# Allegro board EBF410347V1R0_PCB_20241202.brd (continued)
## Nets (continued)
GND: C3.2 C4.2 C5.2 C6.2 C7.2 C8.2 C9.2 C13.2 C14.2 C16.2 C17.2 C18.2 C19.2 C20.2 C21.2 C23.2 C24.2 C26.2 C27.2 C28.2 C29.2 C30.2 C31.2 C32.2 C33.2 C35.1 C36.2 C37.2 C38.2 C39.2 C40.2 C41.2 C42.2 C43.2 C44.2 C45.2 C47.1 C48.2 C49.2 C50.2 C51.2 C52.2 C53.2 C62.1 C65.2 C66.2 C67.2 C68.2 C69.2 C70.2 C71.2 C72.2 C73.2 C74.2 C75.2 C76.2 C77.2 C78.2 C79.2 C80.2 C81.2 C82.2 C83.2 C84.2 C85.2 C86.2 C87.2 C88.2 C89.2 C90.2 C91.2 C92.2 C93.2 C94.2 C95.2 C96.2 C97.2 C98.2 C99.2 C100.2 C101.2 C102.2 C103.2 C104.2 C105.2 C106.2 C107.2 C108.2 C109.2 C110.2 C111.2 C112.2 C113.2 C115.2 C116.2 C117.2 C118.2 C119.2 C120.2 C121.2 C122.2 C123.2 C124.2 C125.2 C126.2 C127.2 C128.2 C129.2 C130.2 C131.2 C132.2 C133.2 C134.2 C135.2 C136.2 C137.2 C138.2 C139.2 C140.2 C141.2 C142.2 C143.2 C144.2 C145.2 C146.2 C147.2 C150.2 C153.2 C154.2 C155.2 C156.2 C157.2 C158.2 C159.2 C160.2 C161.2 C162.2 C164.2 C165.2 CN1.2 CN1.3 D1.2 D2.2 D3.2 D4.2 D5.2 D6.2 D7.2 D8.2 D9.1 D10.1 D11.1 D12.1 D13.1 D14.1 D15.1 D16.1 D17.2 D18.2 D19.2 D20.2 D21.2 D22.2 D23.2 D24.2 D25.2 D26.2 D27.2 D28.2 D29.2 D30.2 D31.2 D32.2 D33.2 D34.2 D35.2 D36.2 D37.2 D38.2 D39.2 D40.2 D41.2 D42.2 D44.1 D47.2(A) D48.2 D49.2 D50.2 D51.2 D52.2 D53.2 D55.2 D56.2 D57.2 D58.2 D59.2 D60.2 D61.2 D62.2 D63.2 D64.2 D65.2 D67.2 D68.2 D69.2 D70.2 D71.2 D72.2 D73.2 D74.2 D75.2 D76.2 J1.2 J1.3 J2.1 J2.2 J2.5(SH1) J2.6(SH2) J3.3 J3.4 J3.6 J3.10 J3.14 J3.17 J3.20 J3.24 J3.29 J3.37 J3.50 J3.53 J3.75 J3.84 J3.87 J3.92 J3.95 J3.98 J3.101 J3.106 J3.109 J3.114 J3.117 J3.122 J3.125 J3.130 J3.133 J3.136 J3.145 J3.146 J3.147 J3.150 J3.151 J3.154 J3.157 J3.160 J3.163 J3.166 J3.173 J3.181 J3.187 J3.192 J3.195 J5.2 J7.6(VSS) J7.10(GND10) J7.11(GND11) J7.12(GND12) J7.13(GND13) J8.5(SH1) J8.6(SH2) J9.4(GND1) J9.7(GND2) J11.2 J12.4(GND) J13.4(GND) J14.1 J14.5(SH1) J14.6(SH2) J15.3 J16.4 J17.4 J17.5 J17.6 J17.13 J17.14 J17.25 J17.26 J18.6 J18.7 J18.8 J18.16 J18.19 J18.22 J18.25 J18.28 J18.31(SH1) J18.32(SH2) J19.1 J19.7(SH1) J19.8(SH2) J21.2 J21.5 J21.7(SH1) J21.8(SH2) J22.1 J22.7(SH1) J22.8(SH2) J23.2 J24.4 J24.23 J24.24 J24.25(SH1) J24.26(SH2) J25.2 J26.8 J26.9(SH1) J26.10(SH2) J27.7 J27.8 J28.4 J28.23 J28.24 J28.25(SH1) J28.26(SH2) J29.4 J29.23 J29.24 J29.25(SH1) J29.26(SH2) J30.4 J30.23 J30.24 J30.25(SH1) J30.26(SH2) J31.5 J31.6 J31.7(SH1) J31.8(SH2) J32.4 J33.4 J33.5(SH1) J33.6(SH2) J34.4 J34.5(SH1) J34.6(SH2) J35.4 J36.4 J37.4 J37.5(SH1) J37.6(SH2) J38.1 J38.5(SH1) J38.6(SH2) L2.2 L10.1 L11.1 L12.1 LED1.1(CATHODE) Q2.2(EMITTER) R2.2 R4.2 R7.2 R9.2 R11.2 R16.2 R17.2 R27.1 R28.2 R29.2 R38.1 R40.2 R50.2 R51.1 R57.2 R59.2 R66.2 R68.2 R76.1 R77.1 R85.2 R111.2 R112.2 R121.2 R122.2 R129.2 R138.2 R163.2 R173.2 R180.2 R181.2 SS1.1(NC_1) SS2.1(NC_1) SS3.1(NC_1) SS4.1(NC_1) SW1.3(B1) SW1.4(B2) T2.1 T2.3 T4.1 T4.3 T6.1 T6.3 T8.1 T8.3 U1.1(GND) U2.1(GND) U3.1(GND) U4.1(GND) U5.7(GND) U5.9(EPAD) U6.7(GND) U6.9(EPAD) U7.2(GND) U8.25(VSS) U9.2(GND) U10.5(GND) U10.9(RESERVE) U10.37(VSS_PLL) U10.49(EPAD) U11.1(\\O\E) U11.3(GND) U12.1(\\O\E) U12.3(GND) U13.2(GND) U14.2(GND) U15.4(VSS) U16.1(GND1) U16.3(GND3) U16.20(GND20) U16.31(GND31) U16.33(GND33) U16.36(GND36) U17.2(A1) U17.3(A2) U17.12(GND) U18.2(GND) U18.8(S) U19.2(GND) U19.8(S) U21.2(GND) U22.2(GND) U23.15(GND) U24.5(GND) U25.15(GND) U26.5(GND) U27.2(GND) Y1.2(GND1) Y1.4(GND2) Y2.2(GND) Y4.2(GND)
VCC3V3_SD: C52.1 C53.1 D8.1 J3.8 J7.4(VDD)
VCC3V3_WIFI: C121.1 C122.1 C123.1 C124.1 C125.1 C126.1 C127.1 R151.1 R164.1 R167.2 U16.9(VDD33) U16.22(VDDIO) Y4.4(VCC)
VCC5V0_SYS: C12.2 C13.1 C14.1 J3.1 J3.2 L3.2 R5.2 R12.1
VCC5V0_USB: C15.2 C16.1 C17.1 L4.2 R6.2 U7.5(IN) U9.5(IN)
VCC5V0_USB20_HUB: C75.1 C76.1 C78.1 C79.1 C80.1 C137.1 J12.1(VBUS) J13.1(VBUS) J14.4 J38.4 U9.1(OUT)
VCC_LVDS: J17.1 J17.2 J17.3 J20.2 J20.4 J20.6
VCC_RTC: C117.1 D43.3 R130.1 R131.1 U15.8(VDD)
VCCA_1V8: J3.7 J26.1 J27.1 R171.1
VCCIO_ACODEC: J3.9 R18.2
VDD_3V3: C23.1 C24.1 C25.2 C68.1 C81.1 C85.1 C106.1 C107.1 C110.1 C111.1 C128.1 C136.1 C141.1 C157.1 C159.1 C160.1 D42.1 D43.2 J19.6 J21.4 L5.2 L13.1 L14.2 L15.1 L16.2 L17.1 R10.2 R13.1 R14.2 R15.2 R31.2 R60.1 R78.1 R80.1 R82.1 R167.1 R174.1 R175.1 R188.1 R189.1 R190.1 R191.1 R192.1 R260.1 U11.5(VCC) U12.5(VCC) U14.5(IN) U17.24(VCC) U18.5(VIO) U19.5(VIO) U21.1(VCCA) U21.5(DIR) U22.1(VCCA) U22.5(DIR) U27.1(VIN) U27.3(EN)
VDD_5V: C2.2 C3.1 C4.1 C132.1 C143.1 C158.1 C161.1 L1.2 R1.2 R21.1 R32.1 R84.1 R132.1 R168.1 R169.1 R170.1 R172.1 R259.1 U13.5(IN) U18.3(VCC) U19.3(VCC) U21.6(VCCB) U22.6(VCCB)
VDD_CAM0_5V: C108.1 C109.1 J24.1 J24.2 J24.3 R172.2
VDD_CAM1_5V: C129.1 C130.1 J28.1 J28.2 J28.3 R168.2
VDD_CAM2_5V: C134.1 C135.1 J29.1 J29.2 J29.3 R170.2
VDD_CAM3_5V: C131.1 C133.1 J30.1 J30.2 J30.3 R169.2
VDD_IO: D75.1 J22.6 R259.2 R260.2
VDD_LCD_3V3: C82.1 C139.1 C140.1 J18.4 J18.5 R176.1 R177.1 U14.1(OUT)
VDD_LCD_5V: C83.1 C84.1 C86.1 J18.1 J18.2 J18.3 U13.1(OUT)
VDD_LVDS: C100.1 C101.1 C102.1 C103.1 C142.1 C164.1 U10.35(VDD_LVDS1) U10.36(VDD_PLL) U10.38(VDD_LVDS2) U27.5(VOUT) Y2.4(VCC)
VDDIO_LVDS: C91.1 C92.1 C93.1 C94.1 C112.1 C113.1 L13.2 R73.1 U10.10(VDDIO) U10.13(VDD_RX)
BAT_RTC: C116.1 D43.1 D44.2 J23.1
BT_HOST_WAKE: J3.46 R158.1
BT_REG_ON: J3.47 R155.2
BT_UART_CTS: R154.2 U16.44(UART_CTS_N)
BT_UART_RTS: R129.1 R150.2 U16.41(UART_RTS_N)
BT_UART_RXD: R153.2 U16.43(UART_RXD)
BT_UART_TXD: R152.2 U16.42(UART_TXD)
BT_WAKE: J3.45 R156.1
CAM0_NRST: J24.22 U17.5(P0_1)
CAM0_PWDN: J24.15 U17.4(P0_0)
CAM1_NRST: J28.22 U17.7(P0_3)
CAM1_PWDN: J28.15 U17.6(P0_2)
CAM2_NRST: J29.22 U17.9(P0_5)
CAM2_PWDN: J29.15 U17.8(P0_4)
CAM3_NRST: J30.22 U17.11(P0_7)
CAM3_PWDN: J30.15 U17.10(P0_6)
CAN0_H: R237.1 R238.1 U18.7(CANH)
CAN0_L: R237.2 R251.1 U18.6(CANL)
CAN0_RX_M2: R240.1 R243.2
CAN0_TX_M2: R239.1 R241.2
CAN1_H: R247.1 R252.1 U19.7(CANH)
CAN1_L: R247.2 R258.1 U19.6(CANL)
CAN1_RX_M1: R246.1 R257.2
CAN1_TX_M1: R245.1 R248.2
CLK_32K_IN: J3.200 R135.2
DGB_RX: D30.1 J15.2 R70.1
DGB_TX: D31.1 J15.1 R69.1
ETH_PHY_LED1: J3.164 J10.10(LED_Y+)
ETH_PHY_LED2: J3.165 J10.12(LED_G+)
ETH_PHY_MDIN0: C55.1 J3.153
ETH_PHY_MDIN1: C57.1 J3.156
ETH_PHY_MDIN2: C59.1 J3.159
ETH_PHY_MDIN3: C61.1 J3.162
ETH_PHY_MDIP0: C54.1 J3.152
ETH_PHY_MDIP1: C56.1 J3.155
ETH_PHY_MDIP2: C58.1 J3.158
ETH_PHY_MDIP3: C60.1 J3.161
EXT_PWR_EN: J3.13 R3.2
FAN_CTRL: J3.40 R137.1
GM8775C_DA0N: R89.2 U10.15(DA0N)
GM8775C_DA0P: R86.2 U10.14(DA0P)
GM8775C_DA1N: R93.2 U10.17(DA1N)
GM8775C_DA1P: R90.2 U10.16(DA1P)
GM8775C_DA2N: R97.2 U10.21(DA2N)
GM8775C_DA2P: R94.2 U10.20(DA2P)
GM8775C_DA3N: R102.2 U10.23(DA3N)
GM8775C_DA3P: R99.2 U10.22(DA3P)
GM8775C_DACN: R107.2 U10.19(DACN)
GM8775C_DACP: R104.2 U10.18(DACP)
GM8775C_RSTN: C95.1 R73.2 R187.2 U10.12(EN)
GPIO0_C0: J3.38 R248.1 R253.1
GPIO0_C1: J3.39 R255.1 R257.1
GPIO0_C6: J3.43 R241.1 R242.1
GPIO0_C7: J3.44 R243.1 R244.1
GPIO0C0: R253.2 R254.1
GPIO0C1: R255.2 R256.1
GPIO0C6: R242.2 R249.1
GPIO0C7: R244.2 R250.1
HP_BUTTON_DET: C40.1 J3.33 R26.2 R29.1
HP_PLUG_IN_DET: J3.196 R36.2
HP_SNS: J3.22 R38.2
HPL_OUT: C34.1 J3.21 R33.2
HPR_OUT: C46.1 J3.23 R34.2
I2C0_SCL: J3.194 J24.6 U15.6(SCL) U17.22(SCL)
I2C0_SDA: J3.193 J24.5 U15.5(SDA) U17.23(SDA)
I2C1_SCL_M1: J3.57 J18.9 J19.4 J28.6 R74.1 R174.2
I2C1_SDA_M1: J3.58 J18.10 J19.5 J28.5 R75.1 R175.2
I2C2_SCL_M1: J3.55 J29.6 R189.2
I2C2_SDA_M1: J3.56 J29.5 R190.2
I2C5_SCL_M1: J3.148 J30.6 R191.2
I2C5_SDA_M1: J3.149 J30.5 R192.2
I2S2_LRCK_M0: J3.182 R157.2
I2S2_SCLK_M0: J3.184 R160.2
I2S2_SDI_M0: J3.185 R161.2
I2S2_SDO_M0: J3.186 R159.2
IO0_C0: D74.1 J22.5 R252.2 R254.2
IO0_C1: D37.1 J22.4 R256.2 R258.2
IO0_C6: D36.1 J22.3 R238.2 R249.2
IO0_C7: D35.1 J22.2 R250.2 R251.2
LCD_BL_PWM: J3.64 R184.1 R185.1
LCD_CPT_INT: J3.60 R81.1 R178.1
LCD_CPT_RST: J3.59 R182.1 R183.1
LCD_RST: J3.63 R186.1 R187.1
LED_BLUE: J3.183 R103.1
LED_RED: R98.1 U17.13(P1_0)
LVDS_3V3: C96.1 C97.1 J20.5 R78.2
LVDS_5V: C104.1 C105.1 J20.3 R84.2
LVDS_12V: C98.1 C99.1 J20.1 J31.1 J31.2 R79.2
LVDS_BL_EN: J3.54 R213.1 U21.3(A1)
LVDS_BL_PWM: R185.2 R214.1 U22.3(A1)
LVDS_BLEN: J31.3 R213.2 R215.2
LVDS_BLPWM: J31.4 R214.2 R216.2
LVDS_CPT_INT: J19.3 R80.2 R178.2
LVDS_CPT_RST: J19.2 R82.2 R183.2
LVDS_TXA_CLKN: J17.15 U10.27(A_CLKN)
LVDS_TXA_CLKP: J17.16 U10.28(A_CLKP)
LVDS_TXA_D0N: J17.7 U10.33(A_Y0N)
LVDS_TXA_D0P: J17.8 U10.34(A_Y0P)
LVDS_TXA_D1N: J17.9 U10.31(A_Y1N)
LVDS_TXA_D1P: J17.10 U10.32(A_Y1P)
LVDS_TXA_D2N: J17.11 U10.29(A_Y2N)
LVDS_TXA_D2P: J17.12 U10.30(A_Y2P)
LVDS_TXA_D3N: J17.17 U10.25(A_Y3N)
LVDS_TXA_D3P: J17.18 U10.26(A_Y3P)
LVDS_TXB_CLKN: J17.27 U10.41(B_CLKN)
LVDS_TXB_CLKP: J17.28 U10.42(B_CLKP)
LVDS_TXB_D0N: J17.19 U10.47(B_Y0N)
LVDS_TXB_D0P: J17.20 U10.48(B_Y0P)
LVDS_TXB_D1N: J17.21 U10.45(B_Y1N)
LVDS_TXB_D1P: J17.22 U10.46(B_Y1P)
LVDS_TXB_D2N: J17.23 U10.43(B_Y2N)
LVDS_TXB_D2P: J17.24 U10.44(B_Y2P)
LVDS_TXB_D3N: J17.29 U10.39(B_Y3N)
LVDS_TXB_D3P: J17.30 U10.40(B_Y3P)
MASKROM: C165.1 D76.1 R261.2 SW1.1(A1)
MDIN0_RJ45: D10.2 J10.2 T1.2 T2.2
MDIN1_RJ45: D12.2 J10.6 T3.2 T4.2
MDIN2_RJ45: D14.2 J10.5 T5.2 T6.2
MDIN3_RJ45: D16.2 J10.8 T7.2 T8.2
MDIP0_RJ45: D9.2 J10.1 T1.3 T2.4
MDIP1_RJ45: D11.2 J10.3 T3.3 T4.4
MDIP2_RJ45: D13.2 J10.4 T5.3 T6.4
MDIP3_RJ45: D15.2 J10.7 T7.3 T8.4
MIC1_INN: J3.19 J4.1 R27.2
MIC1_INP: J3.18 J4.2 R23.2
MIPI_BL_PWM: J18.13 R184.2
MIPI_CSI_RX0_CLK0N: J3.132 J24.10
MIPI_CSI_RX0_CLK0P: J3.131 J24.9
MIPI_CSI_RX0_CLK1N: J3.124 J28.10
MIPI_CSI_RX0_CLK1P: J3.123 J28.9
MIPI_CSI_RX0_D0N: J3.129 J24.12
MIPI_CSI_RX0_D0P: J3.128 J24.11
MIPI_CSI_RX0_D1N: J3.127 J24.8
MIPI_CSI_RX0_D1P: J3.126 J24.7
MIPI_CSI_RX0_D2N: J3.121 J28.12
MIPI_CSI_RX0_D2P: J3.120 J28.11
MIPI_CSI_RX0_D3N: J3.119 J28.8
MIPI_CSI_RX0_D3P: J3.118 J28.7
MIPI_CSI_RX1_CLK0N: J3.116 J29.10
MIPI_CSI_RX1_CLK0P: J3.115 J29.9
MIPI_CSI_RX1_CLK1N: J3.108 J30.10
MIPI_CSI_RX1_CLK1P: J3.107 J30.9
MIPI_CSI_RX1_D0N: J3.113 J29.12
MIPI_CSI_RX1_D0P: J3.112 J29.11
MIPI_CSI_RX1_D1N: J3.111 J29.8
MIPI_CSI_RX1_D1P: J3.110 J29.7
MIPI_CSI_RX1_D2N: J3.105 J30.12
MIPI_CSI_RX1_D2P: J3.104 J30.11
MIPI_CSI_RX1_D3N: J3.103 J30.8
MIPI_CSI_RX1_D3P: J3.102 J30.7
MIPI_CTP_INT: J18.11 R81.2 R176.2
MIPI_CTP_RST: J18.12 R177.2 R182.2
MIPI_DSI_CLKN: J18.24 R106.2
MIPI_DSI_CLKP: J18.23 R105.2
MIPI_DSI_D0N: J18.27 R88.2
MIPI_DSI_D0P: J18.26 R87.2
MIPI_DSI_D1N: J18.21 R92.2
MIPI_DSI_D1P: J18.20 R91.2
MIPI_DSI_D2N: J18.18 R96.2
MIPI_DSI_D2P: J18.17 R95.2
MIPI_DSI_D3N: J18.30 R101.2
MIPI_DSI_D3P: J18.29 R100.2
MIPI_DSI_TX_CLKN: J3.135 R106.1 R107.1
MIPI_DSI_TX_CLKP: J3.134 R104.1 R105.1
MIPI_DSI_TX_D0N: J3.138 R88.1 R89.1
MIPI_DSI_TX_D0P: J3.137 R86.1 R87.1
MIPI_DSI_TX_D1N: J3.140 R92.1 R93.1
MIPI_DSI_TX_D1P: J3.139 R90.1 R91.1
MIPI_DSI_TX_D2N: J3.142 R96.1 R97.1
MIPI_DSI_TX_D2P: J3.141 R94.1 R95.1
MIPI_DSI_TX_D3N: J3.144 R101.1 R102.1
MIPI_DSI_TX_D3P: J3.143 R99.1 R100.1
MIPI_LCD_PWR_EN: J3.25 R179.1
MIPI_LCD_RST: J18.15 R186.2
ON/OFF_KEY: D46.2 J3.11 R71.2
PCM_CLK: R160.1 U16.26(NC26)
PCM_DIN: R159.1 U16.27(NC27)
PCM_OUT: R161.1 U16.25(NC25)
PCM_SYNC: R157.1 U16.28(NC28)
PWM3_IR: J3.199 R108.1
RECOVERY/ADC_KEY: D34.1 J3.35 J16.3
RESET_KEY: J3.12 R72.2
RS232_1_3V3: C144.1 J32.1 J34.1 L14.1 U23.16(VCC)
RS232_1_R1IN: J34.3 R116.2 U23.13(R1IN)
RS232_1_R2IN: J32.3 R113.2 U23.8(R2IN)
RS232_1_T1OUT: J34.2 R118.2 U23.14(T1OUT)
RS232_1_T2OUT: J32.2 R114.2 U23.7(T2OUT)
RS232_2_3V3: C150.1 J35.1 J37.1 L16.1 U25.16(VCC)
RS232_2_R1IN: J37.3 R126.2 U25.13(R1IN)
RS232_2_R2IN: J35.3 R123.2 U25.8(R2IN)
RS232_2_T1OUT: J37.2 R128.2 U25.14(T1OUT)
RS232_2_T2OUT: J35.2 R124.2 U25.7(T2OUT)
RS485_1_3V3: C153.1 D54.2 J33.1 L15.2 U24.8(VCC)
RS485_1_A: J33.3 R109.1 R110.2 R115.2 U24.6(A)
RS485_1_B: J33.2 R110.1 R112.1 R117.2 U24.7(B)
RS485_1_DIR: J3.62 R111.1 U24.2(R\E\) U24.3(DE)
RS485_2_3V3: C156.1 D66.2 J36.1 L17.2 U26.8(VCC)
RS485_2_A: J36.3 R119.1 R120.2 R125.2 U26.6(A)
RS485_2_B: J36.2 R120.1 R122.1 R127.2 U26.7(B)
RS485_2_DIR: J3.61 R121.1 U26.2(R\E\) U26.3(DE)
RTC_INT: D45.2 J3.197
SARADC0_BOOT: J3.36 R261.1
SARADC0_IN3: J3.34 R171.2 R173.1
SARADC0_IN5: J3.32 R145.2
SARADC0_IN6: J3.31 R146.2
SARADC0_IN7: J3.30 R147.2
SARADC1_IN0: J3.83 R139.2
SARADC1_IN1: J3.82 R140.2
SARADC1_IN2: J3.81 R141.2
SARADC1_IN3: J3.80 R142.2
SARADC1_IN4: J3.79 R143.2
SARADC1_IN5: J3.78 R144.2
SARADC1_IN6: J3.77 R148.2
SARADC1_IN7: J3.76 R149.2
SDMMC0_CLK: J3.179 R46.1
SDMMC0_CMD: J3.178 R45.1
SDMMC0_D0: J3.174 R47.1
SDMMC0_D1: J3.175 R48.1
SDMMC0_D2: J3.176 R43.1
SDMMC0_D3: J3.177 R44.1
SDMMC0_DETN: J3.180 R49.1
SDMMC1_CLK: J3.172 U16.17(SD_CLK)
SDMMC1_CMD: J3.171 U16.16(SD_CMD)
SDMMC1_D0: J3.167 U16.18(SD_D0)
SDMMC1_D1: J3.168 U16.19(SD_D1)
SDMMC1_D2: J3.169 U16.14(SD_D2)
SDMMC1_D3: J3.170 U16.15(SD_D3)
SPK_CTRL: J3.198 R25.1 R39.1
SPK_LN: C38.1 J8.2 L6.2
SPK_LP: C37.1 J8.1 L7.2
SPK_RN: C49.1 J8.3 L8.2
SPK_RP: C48.1 J8.4 L9.2
SPKN_OUT: J3.16 R42.1
SPKP_OUT: J3.15 R41.1
SYS_LED: J3.28 LED2.1(CATHODE)
UART0_RX: R70.2 U12.2(A)
UART0_RX_M0_DEBUG: J3.52 U12.4(Y)
UART0_TX: R69.2 U11.4(Y)
UART0_TX_M0_DEBUG: J3.51 U11.2(A)
UART1_CTSN_M0: J3.191 R150.1
UART1_RTSN_M0: J3.190 R154.1
UART1_RX_M0: J3.189 R152.1
UART1_TX_M0: J3.188 R153.1
UART2_RX_M1: D64.1 J3.27 R116.1 U23.12(R1OUT)
UART2_TX_M1: D65.1 J3.26 R118.1 U23.11(T1IN)
UART3_RX_M1: D62.1 J3.65 R113.1 U23.9(R2OUT)
UART3_TX_M1: D63.1 J3.66 R114.1 U23.10(T2IN)
UART4_RX_M0: D71.1 J3.67 R126.1 U25.12(R1OUT)
UART4_TX_M0: D72.1 J3.68 R128.1 U25.11(T1IN)
UART7_RX_M0: D69.1 J3.69 R123.1 U25.9(R2OUT)
UART7_TX_M0: D70.1 J3.70 R124.1 U25.10(T2IN)
UART8_RX_M0: D60.1 J3.71 R115.1 U24.1(RXD)
UART8_TX_M0: D61.1 J3.72 R117.1 U24.4(TXD)
UART9_RX_M1: D67.1 J3.73 R125.1 U26.1(RXD)
UART9_TX_M1: D68.1 J3.74 R127.1 U26.4(TXD)
USB20_HOST1_DM: J3.94 R65.2
USB20_HOST1_DP: J3.93 R64.2
USB20_HUB_PWR_EN: J3.42 R67.1
USB30_DM: D17.1 J9.2(D-) R52.1
USB30_DP: D18.1 J9.3(D+) R53.1
USB30_OTG0_DM: J3.97 R52.2
USB30_OTG0_DP: J3.96 R53.2
USB30_OTG0_ID: J3.99 R193.2
USB30_OTG0_SSRXN: J3.89 R54.2
USB30_OTG0_SSRXP: J3.88 R55.2
USB30_OTG0_SSTXN: C63.2 J3.91
USB30_OTG0_SSTXP: C64.2 J3.90
USB30_OTG0_VBUSDET: J3.100 R58.2 R59.1
USB30_OTG_PWR_EN: J3.41 R56.1
USB30_OTG_VBUS: C66.1 C67.1 J9.1(VBUS) R58.1 U7.1(OUT)
USB30_RXN: D19.1 J9.5(RX-) R54.1
USB30_RXP: D20.1 J9.6(RX+) R55.1
USB30_TXN: C63.1 D21.1 J9.8(TX-)
USB30_TXP: C64.1 D22.1 J9.9(TX+)
USB_HUB_3V3: C69.1 C70.1 C71.1 R60.2 R61.2 R62.2 R63.2 U8.1(OVCJ) U8.20(VDD33F)
USB_HUB_DM1: D24.1 J12.2(D-) U8.11(DM1)
USB_HUB_DM2: D26.1 J13.2(D-) U8.9(DM2)
USB_HUB_DM3: D28.1 J14.3 U8.7(DM3)
USB_HUB_DM4: D38.1 J38.3 U8.5(DM4)
USB_HUB_DP1: D25.1 J12.3(D+) U8.12(DP1)
USB_HUB_DP2: D27.1 J13.3(D+) U8.10(DP2)
USB_HUB_DP3: D29.1 J14.2 U8.8(DP3)
USB_HUB_DP4: D73.1 J38.2 U8.6(DP4)
WL_HOST_WAKE: J3.49 R166.1
WL_REG_ON: J3.48 R165.1
N16722097: C10.1 U2.6(BOOT)
N16722109: C10.2 L3.1 U2.2(SW)
N16722129: C12.1 R5.1 R9.1 U2.4(FB)
N16722243: R7.1 R8.1 U2.5(EN)
N16722849: J1.1 J1.5 L2.1
N16722969: C25.1 R14.1 R17.1 U4.4(FB)
N16722987: C22.2 L5.1 U4.2(SW)
N16723079: C22.1 U4.6(BOOT)
N16723587: C1.1 U1.6(BOOT)
N16723611: C1.2 L1.1 U1.2(SW)
N16723631: C2.1 R1.1 R4.1 U1.4(FB)
N16724039: R10.1 U3.5(EN)
N16724119: C11.1 U3.6(BOOT)
N16724131: C11.2 L4.1 U3.2(SW)
N16724163: C15.1 R6.1 R11.1 U3.4(FB)
N16724623: LED2.2(ANODE) R13.2
N16724791: LED1.2(ANODE) R12.2
N16783121: D7.1 J7.1(DAT2) R43.2
N16783123: D3.1 J7.7(DAT0) R47.2
N16783125: D4.1 J7.5(CLK) R46.2
N16783127: D5.1 J7.3(CMD) R45.2
N16783129: D6.1 J7.2(CD/DAT3) R44.2
N16783131: D2.1 J7.8(DAT1) R48.2
N16783147: D1.1 J7.9(CD) R49.2
N16783231: J6.1 R41.2
N16783233: J6.2 R42.2
N16783279: C28.1 C29.1 C30.1 C31.1 C32.1 R19.2 R21.2 U5.6(VDD)
N16783471: C41.1 C42.1 C43.1 C44.1 C45.1 R30.2 R32.2 U6.6(VDD)
N16783658: R25.2 R28.1 U5.1(CTRL)
N16783744: R22.2 U5.4(INN)
N16783769: R24.2 U5.3(INP)
N16783771: C34.2 R22.1
N16783785: C35.2 R24.1
N16783804: L7.1 U5.8(VOP)
N16783806: L6.1 U5.5(VON)
N16783823: C39.1 U5.2(BYPASS)
N16783940: R39.2 R40.1 U6.1(CTRL)
N16784027: R35.2 U6.4(INN)
N16784039: R37.2 U6.3(INP)
N16784051: C46.2 R35.1
N16784053: C47.2 R37.1
N16784084: L9.1 U6.8(VOP)
N16784086: L8.1 U6.5(VON)
N16784100: C51.1 U6.2(BYPASS)
N16784225: C50.1 J5.6 R31.1 R36.1
N16784316: C36.1 J5.1 R20.2 R23.1 R26.1
N16784333: C33.1 R18.1 R20.1
N16784429: J5.3 R34.1
N16784431: J5.4 R33.1
N16786732: R2.1 R3.1 U4.5(EN)
N16786936: R15.1 U1.5(EN)
N16788412: C54.2 T1.4
N16788414: C55.2 T1.1
N16788463: C56.2 T3.4
N16788475: C57.2 T3.1
N16788524: C58.2 T5.4
N16788526: C59.2 T5.1
N16788585: C60.2 T7.4
N16788587: C61.2 T7.1
N16792936: J10.9(LED_Y-) R16.1
N16792940: C62.2 J10.13(SH1) J10.14(SH2) R51.2
N16793616: J10.11(LED_G-) R50.1
N16801073: J9.10(SH1) J9.11(SH2) L10.2
N16801211: C65.1 R56.2 U7.4(EN)
N16801228: R57.1 U7.3(ISET)
N16802593: D23.1 J11.1 R193.1
N16803235: R64.1 U8.15(DPU)
N16803237: R65.1 U8.14(DMU)
N16803510: C73.1 U8.3(XOUT) Y1.1
N16803514: C74.1 U8.4(XIN) Y1.3
N16803540: R66.1 U8.13(REXT)
N16803549: C72.1 R61.1 U8.17(VBUSM)
N16803553: R63.1 U8.16(XRSTJ)
N16803559: R62.1 U8.18(BUSJ)
N16804913: J12.5(SHELL_1) J12.6(SHELL_2) L11.2
N16810803: C77.1 R67.2 U9.4(EN)
N16810815: R68.1 U9.3(ISET)
N16816847: D33.1 J16.2 R72.1
N16816849: D32.1 J16.1 R71.1
N16821329: C87.1 C88.1 C89.1 C90.1 U10.11(VCORE)
N16823430: R83.2 R85.1 U10.24(REFCLK)
N16823432: R83.1 Y2.3(CLK)
N16823570: R76.2 U10.8(I2C_TYPE)
N16823572: R77.2 U10.7(I2C_ADDR)
N16823879: R74.2 U10.1(SCL)
N16823895: R75.2 U10.2(SDA)
N16825657: D53.1 J26.2 R139.1
N16825664: D52.1 J26.3 R140.1
N16825671: D51.1 J26.4 R141.1
N16825678: D50.1 J26.5 R142.1
N16825685: D49.1 J26.6 R143.1
N16825692: D48.1 J26.7 R144.1
N16827764: D59.1 J27.2 R145.1
N16827766: D58.1 J27.3 R146.1
N16827768: D57.1 J27.4 R147.1
N16827770: D56.1 J27.5 R148.1
N16827772: D55.1 J27.6 R149.1
N16832694: C114.2 C120.1 U16.2(WL_BT_ANT)
N16832701: C114.1 C115.1 CN1.1
N16832725: R156.2 U16.6(BT_WAKE)
N16832727: R158.2 U16.7(BT_HOST_WAKE)
N16832815: R164.2 R165.2 U16.12(WL_REG_ON)
N16832856: R166.2 U16.13(WL_HOST_WAKE)
N16833042: R162.2 R163.1 Y4.3(CLK)
N16833048: R162.1 U16.24(LPO)
N16833114: R151.2 R155.1 U16.34(BT_RST_N)
N16853010: D45.1 D46.1 R130.2 U15.3(\\I\N\T)
N16853145: C119.1 U15.2(OSCO) Y3.2
N16853170: C118.1 U15.1(OSCI) Y3.1
N16853193: R131.2 R135.1 U15.7(CLKOUT)
N16853900: Q1.1(GATE) Q2.3(COLLECTOR) R136.2
N16853902: Q2.1(BASE) R137.2 R138.1
N16853946: D47.1(K) J25.1 R134.2
N16853981: Q1.2(SOURCE) R132.2 R133.2 R136.1
N16854018: Q1.3(DRAIN) R134.1
N16869660: C151.1 U25.3(C1-)
N16869662: C151.2 U25.1(C1+)
N16869664: C152.1 U25.5(C2-)
N16869666: C152.2 U25.4(C2+)
N16869668: C155.1 U25.6(V-)
N16869670: C154.1 U25.2(V+)
N16869989: D66.1 R119.2
N16870097: D54.1 R109.2
N16870438: C148.1 U23.3(C1-)
N16870440: C148.2 U23.1(C1+)
N16870442: C149.1 U23.5(C2-)
N16870444: C149.2 U23.4(C2+)
N16870446: C147.1 U23.6(V-)
N16870448: C146.1 U23.2(V+)
N16880008: C162.1 U27.4(BP)
N16948483: J13.5(SHELL_1) J13.6(SHELL_2) L12.2
N16990717: D39.1 J21.1 R98.2
N16990719: D40.1 J21.3 R103.2
N16990803: D41.1 J21.6 R108.2
N16991546: R188.2 U17.21(A0)
N17000237: R215.1 U21.4(B1)
N17000272: R216.1 U22.4(B1)
N17004192: C138.1 C145.1 R179.2 U13.4(EN) U14.4(EN)
N17004200: R180.1 U13.3(ISET)
N17004297: R181.1 U14.3(ISET)
N17012559: R239.2 U18.1(TXD)
N17012562: R240.2 U18.4(RXD)
N17015515: R245.2 U19.1(TXD)
N17015527: R246.2 U19.4(RXD)

Pads without a net: J3 5 85 86; J5 7 8; J18 14; J24 13 14 16 17 18 19 20 21; J28 13 14 16 17 18 19 20 21; J29 13 14 16 17 18 19 20 21; J30 13 14 16 17 18 19 20 21; NOREF 1; NOREF#3 1; NOREF#5 1; NOREF#7 1; NOREF#8 1; NOREF#9 1; NOREF#10 1; NOREF#11 1; NOREF#12 1; NOREF#13 1; NOREF#14 1; NOREF#15 1; NOREF#16 1; NOREF#17 1; NOREF#18 1; SW1 2; U8 2 19 21 22 23 24; U10 3 4 6; U16 4 5 8 10 11 21 23 29 30 32 35 37 38 39 40 45 46 47; U17 1 14 15 16 17 18 19 20; Y2 1; Y4 1

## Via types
v1: diameter 0.508, hole 0.254, TOP to BOTTOM, 1432 vias

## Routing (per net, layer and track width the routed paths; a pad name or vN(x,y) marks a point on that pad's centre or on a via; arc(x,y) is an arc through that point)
12V: length 15.8
  BOTTOM w0.254: 20.83,67.44 22.33,67.44 R8.2 ; 25.68,42.44 v1(25.68,42.43)
  BOTTOM w0.381: R133.1 v1(123.97,47.75) ; R19.1 26.8,42.32 v1(26.68,42.43) ; R30.1 16.55,43.05 25.07,43.05 25.68,42.44
  vias: v1(13.15,64.83) v1(15.15,64.83) v1(15.15,63.83) v1(16.15,65.83) v1(16.15,64.83) v1(18.65,66.83) v1(19.65,66.83) v1(19.65,65.83) v1(20.65,66.83) v1(20.65,65.83) v1(20.65,64.83) v1(32.89,21.99) v1(32.89,20.99)
GND: length 899
  TOP w0.203: U21.2 18.41,44.02 v1(18.44,43.99) ; v1(26.14,27.03) 26.52,27.41 U10.9 ; v1(18.44,48.94) 18.41,48.97 U22.2 ; U10.5 v1(29.71,25.41) ; v1(23.14,25.03) 23.14,23.93 22.65,23.43 U10.37
  TOP w0.254: D73.2 v1(116.93,43.14) ; C147.2 v1(97.92,33.61) ; C77.2 111.46,53.1 v1(111.36,53.2) ; C146.2 v1(88.74,33.61) ; v1(5.43,75.51) v1(5.43,74.51) 5.43,73.26 5.68,73.01 C85.2 ; J7.6 v1(61.79,73.1) ; J38.1 v1(118.91,44.3) ; v1(86.5,56.7) 85.6,55.8 J3.37 ; R66.2 v1(93.93,67.66) ; 90.76,55.83 90.75,55.82 Y1.4 89.83,54.98 89.82,54.96 89.82,52.86 89.98,52.7 93.07,52.7 ; R76.1 R77.1 ; R76.1 C93.2 v1(32.89,27.05) ; R76.1 v1(32.89,26.03) ; C38.2 C37.2 12.57,38.49 v1(12.57,37.46) U5.7 ; D31.2 v1(5.08,79.74) ; D36.2 v1(116.2,34.85) ; J3.10 85.16,31.5 v1(85.46,31.2) ; D70.2 v1(110.59,45.73) ; J3.24 83.99,44.2 82.96,44.2 v1(82.86,44.3) ; D35.2 v1(116.2,33.7) ; U16.31 v1(111.36,54.2) ; C144.2 v1(90.06,38.49) ; v1(16.7,35.43) 16.93,35.2 Y2.2 15.84,34.48 15.8,34.44 ; v1(16.7,35.43) v1(17.7,35.43) v1(18.7,35.43) v1(19.7,35.43) 19.83,35.43 20.16,35.1 20.16,32.11 20.23,32.04 20.23,31.79 v1(20.4,31.62) R85.2 ; v1(16.7,35.43) 16.13,35.43 15.8,35.1 15.8,34.44 ; C116.2 116.32,58.71 v1(115.87,58.71) U16.36 ; v1(32.89,29.08) C90.2 C95.2 C94.2 C113.2 ; C124.2 v1(98.33,56.89) ; U16.1 v1(113.16,69.37) ; 106.81,48.26 106.79,48.27 Y4.2 105.88,47.3 105.87,47.29 ; 106.81,48.26 106.81,47.69 106.61,47.49 102.81,47.49 102.65,47.66 102.65,51.25 C123.2 103.58,52.9 103.63,52.95 v1(103.63,52.97) ; 106.81,48.26 106.81,51.25 R163.2 v1(105.87,52.95) ; C150.2 103.39,38.49 v1(103.68,38.78) ; C111.2 31.12,35.36 ; J21.5 v1(72.4,14.5) ; R129.2 v1(119.7,62.1) ; 93.98,53.49 93.98,55.81 v1(93.4,56.4) C74.2 ; 93.98,53.49 93.97,53.48 Y1.2 93.05,52.72 93.07,52.7 ; 93.98,53.49 93.98,52.9 93.78,52.7 93.07,52.7 ; v1(18.44,43.99) 18.44,43.78 C128.2 19.51,42.71 v1(19.51,42.16) ; v1(100.85,70.1) 100.84,70.12 D24.2 ; U13.2 v1(13.34,20.32) ; D28.2 116.93,51.94 v1(116.97,51.89) ; J3.14 85.36,35.1 v1(85.46,35.2) ; v1(15.54,27.55) 15.54,27.56 U27.2 ; C72.2 v1(89.87,67.66) ; D29.2 v1(116.93,55.21) ; v1(103.97,58.71) U16.20 ; C68.2 v1(88.83,53.73) ; L11.1 v1(93.6,69.62) ; C132.2 19.19,46.61 v1(19.92,47.34) 18.99,48.26 C136.2 18.44,48.73 v1(18.44,48.94) ; J21.2 v1(78.4,14.5) ; U23.15 v1(91.84,40.26) ; J3.173 v1(57.79,22.63) ; D25.2 99.44,70.12 v1(99.46,70.1) ; C80.2 102.49,70.12 v1(102.51,70.1) ; C49.2 C48.2 13.84,43.17 v1(13.84,44.19) U6.7 ; 15.8,34.44 v1(15.8,32.69) ; D71.2 v1(105.51,45.73) ; D37.2 v1(116.2,35.99) ; C73.2 C70.2 ; 38.06,36.22 37.84,36 J3.136 ; v1(8.12,77.6) 7.77,77.25 U11.1 ; U11.3 6.47,77.25 v1(6.12,77.6) ; v1(27.03,44.98) 27.03,44.98 U17.12 ; R68.2 112.85,52.89 v1(113.16,53.2) ; D74.2 v1(116.2,37.13) ; U14.2 v1(13.08,24) v1(12.08,24) ; C126.2 v1(97.89,60.2) ; U9.2 113.97,48.89 ; J22.1 v1(118.91,32.05) ; C137.2 v1(116.2,38.3) ; D65.2 v1(94.26,45.73) ; U16.3 v1(111.36,68.87) ; D63.2 v1(96.92,45.73) ; U16.33 v1(113.16,54.2) ; v1(0.78,71.27) 0.77,71.26 ; D62.2 v1(99.46,45.73) ; C121.2 v1(104.95,72.62) ; C125.2 v1(98.33,57.91) ; C71.2 v1(87.84,63.9) ; D72.2 v1(108.05,45.73) ; C89.2 v1(32.89,28.07) ; C122.2 v1(105.96,72.62) ; C127.2 v1(98.33,58.93) ; U12.3 v1(2.28,77.6)
  TOP w0.508: 127.44,35.47 J38.5 ; J38.5 127.44,36.63 ; J38.5 125.76,36.05 ; J17.26 22.75,15.2 ; J17.26 21.88,14.32 ; J17.26 21.88,16.08 ; J17.26 21,15.2 ; J9.4 72.67,75.9 ; J9.4 71.94,75.17 ; J9.4 73.4,75.17 ; J27.8 116.67,29.3 ; J27.8 116.67,27.85 ; J27.8 115.95,28.57 ; J27.8 117.4,28.57 ; 105.44,21.84 J35.4 ; J35.4 106.17,22.57 ; J35.4 106.89,21.84 ; J35.4 106.17,21.12 ; 42.02,82.5 J5.2 ; J5.2 42.8,81.32 ; J5.2 42.8,83.68 ; J5.2 43.57,82.5 ; J33.5 109.49,10.06 ; J33.5 108.34,10.06 ; J33.5 108.92,11.74 ; 75.44,73.67 J9.7 ; J9.7 76.17,74.4 ; J9.7 76.9,73.67 ; J9.7 76.17,72.94 ; 67.58,10.06 J21.7 ; J21.7 68.73,10.06 ; J21.7 68.15,11.74 ; J21.8 82.65,11.74 ; J21.8 83.23,10.06 ; J21.8 82.08,10.06 ; 125.76,46.55 J38.6 ; J38.6 127.44,47.13 ; J38.6 127.44,45.97 ; 2.05,37.97 J31.8 ; J31.8 2.05,39.13 ; J31.8 3.73,38.55 ; J26.9 47.9,11.74 ; J26.9 48.48,10.06 ; J26.9 47.32,10.06 ; J8.5 2.05,37.37 ; J8.5 2.05,36.22 ; J8.5 3.73,36.8 ; J25.2 126.39,64.32 ; J25.2 125.69,63.61 ; J25.2 127.09,63.61 ; 33.88,16.32 J17.13 ; J17.13 34.75,17.2 ; J17.13 33,17.2 ; J17.13 33.88,18.08 ; J33.6 119.42,11.74 ; J33.6 118.84,10.06 ; J33.6 119.99,10.06 ; 95.66,27.85 J16.4 ; J16.4 95.66,29.3 ; J16.4 94.93,28.57 ; 115.95,21.84 J36.4 ; J36.4 116.67,21.12 ; J36.4 116.67,22.57 ; J36.4 117.4,21.84 ; J17.6 42.75,15.2 ; J17.6 41,15.2 ; J17.6 41.88,14.32 ; J17.6 41.88,16.08 ; J23.2 122.89,64.12 ; J23.2 122.26,63.49 ; J23.2 123.52,63.49 ; 96.64,75.52 J12.4 ; J12.4 97.62,76.5 ; J12.4 95.66,76.5 ; J12.4 96.64,77.48 ; 2.28,82.31 J15.3 ; J15.3 1.3,83.29 ; J15.3 3.25,83.29 ; J15.3 2.28,84.26 ; J34.6 95.49,10.06 ; J34.6 94.91,11.74 ; J34.6 94.33,10.06 ; 41.88,16.32 J17.5 ; J17.5 41.88,18.08 ; J17.5 41,17.2 ; J17.5 42.75,17.2 ; 16.78,11 SS1.1 10.22,11 ; J17.14 33.88,16.08 ; J17.14 33.88,14.32 ; J17.14 34.75,15.2 ; J17.14 33,15.2 ; 0.77,68.29 J2.5 0.77,71.26 ; 125.76,19.8 J22.7 ; J22.7 127.44,20.38 ; J22.7 127.44,19.22 ; 2.05,25.72 J8.6 ; J8.6 3.73,26.3 ; J8.6 2.05,26.87 ; J13.4 113.6,77.48 ; J13.4 114.58,76.5 ; J13.4 112.62,76.5 ; J13.4 113.6,75.52 ; J32.4 96.39,21.84 ; J32.4 95.66,22.57 ; J32.4 94.93,21.84 ; J32.4 95.66,21.12 ; J37.6 107.16,11.74 ; J37.6 106.58,10.06 ; J37.6 107.74,10.06 ; 127.44,47.73 J14.5 ; J14.5 125.76,48.31 ; J14.5 127.44,48.88 ; J11.2 87.85,84.72 ; J11.2 86.87,85.7 ; J11.2 86.87,83.74 ; J11.2 85.89,84.72 ; J37.5 96.66,11.74 ; J37.5 97.24,10.06 ; J37.5 96.08,10.06 ; SS2.1 123.5,14.28 ; SS2.1 126.78,11 ; SS2.1 120.22,11 ; 0.77,56.86 J2.6 0.77,54.71 ; SS3.1 126.78,69 ; SS3.1 123.5,72.28 ; SS3.1 123.5,65.72 ; SS3.1 120.22,69 ; J31.7 2.05,53.63 ; J31.7 2.05,52.47 ; J31.7 3.73,53.05 ; 2.05,9.46 J19.8 ; J19.8 3.73,10.04 ; J19.8 2.05,10.62 ; 13.5,65.72 SS4.1 16.78,69 ; J26.10 66.98,10.06 ; J26.10 66.4,11.74 ; J26.10 65.82,10.06 ; 21.88,16.32 J17.25 22.75,17.2 ; J19.7 2.05,25.12 ; J19.7 2.05,23.96 ; J19.7 3.73,24.54 ; J17.4 43.88,16.08 ; J17.4 43.88,14.32 ; J17.4 44.75,15.2 ; J17.4 43,15.2 ; J14.6 127.44,59.38 ; J14.6 127.44,58.23 ; J14.6 125.76,58.81 ; J27.7 115.4,28.57 ; J27.7 114.67,29.3 ; J27.7 113.95,28.57 ; J27.7 114.67,27.85 ; 125.76,34.3 J22.8 ; J22.8 127.44,34.88 ; J22.8 127.44,33.72 ; 83.83,10.06 J34.5 ; J34.5 84.99,10.06 ; J34.5 84.41,11.74
  GND02 w0.508: J27.7 114.67,29.3 ; J27.7 115.4,28.57 ; J27.7 113.95,28.57 ; J27.7 114.67,27.85 ; J17.5 41.88,18.08 ; J17.5 41,17.2 ; J17.5 41.88,16.32 ; J17.5 42.75,17.2 ; 18.57,77.67 J1.3 ; J1.3 19.3,76.2 ; J1.3 19.3,79.15 ; J1.3 20.03,77.67 ; 94.93,21.84 J32.4 ; J32.4 95.66,21.12 ; J32.4 95.66,22.57 ; J32.4 96.39,21.84 ; J9.4 72.67,75.9 ; J9.4 73.4,75.17 ; J9.4 71.94,75.17 ; 10.22,11 SS1.1 16.78,11 ; J16.4 95.66,29.3 ; J16.4 95.66,27.85 ; J16.4 94.93,28.57 ; J16.4 96.39,28.57 ; 106.17,21.12 J35.4 ; J35.4 106.17,22.57 ; J35.4 106.89,21.84 ; J35.4 105.44,21.84 ; 86.87,83.74 J11.2 ; J11.2 87.85,84.72 ; J11.2 86.87,85.7 ; J11.2 85.89,84.72 ; 1.3,83.29 J15.3 ; J15.3 2.28,84.26 ; J15.3 3.25,83.29 ; J15.3 2.28,82.31 ; 43.88,14.32 J17.4 ; J17.4 43.88,16.08 ; J17.4 44.75,15.2 ; J17.4 43,15.2 ; 33,15.2 J17.14 ; J17.14 33.88,16.08 ; J17.14 33.88,14.32 ; J17.14 34.75,15.2 ; J17.13 34.75,17.2 ; J17.13 33.88,16.32 ; J17.13 33,17.2 ; J17.13 33.88,18.08 ; 122.26,63.49 J23.2 ; J23.2 123.52,63.49 ; J23.2 122.89,64.12 ; J27.8 116.67,29.3 ; J27.8 116.67,27.85 ; J27.8 115.95,28.57 ; J27.8 117.4,28.57 ; SS2.1 126.78,11 ; SS2.1 120.22,11 ; SS2.1 123.5,14.28 ; J9.7 76.17,74.4 ; J9.7 76.9,73.67 ; J9.7 76.17,72.94 ; J9.7 75.44,73.67 ; SS4.1 16.78,69 ; SS4.1 13.5,65.72 ; SS4.1 10.22,69 ; SS4.1 13.5,72.28 ; 42.8,81.32 J5.2 ; J5.2 43.57,82.5 ; J5.2 42.8,83.68 ; J5.2 42.02,82.5 ; 113.6,75.52 J13.4 ; J13.4 114.58,76.5 ; J13.4 113.6,77.48 ; J13.4 112.62,76.5 ; J17.25 22.75,17.2 ; J17.25 21,17.2 ; J17.25 21.88,16.32 ; J17.25 21.88,18.08 ; 13.27,77.67 J1.2 ; J1.2 14,79.15 ; J1.2 14,76.2 ; J1.2 14.73,77.67 ; 120.22,69 SS3.1 ; SS3.1 126.78,69 ; SS3.1 123.5,65.72 ; SS3.1 123.5,72.28 ; 41,15.2 J17.6 ; J17.6 41.88,16.08 ; J17.6 42.75,15.2 ; J17.6 41.88,14.32 ; 96.64,75.52 J12.4 ; J12.4 95.66,76.5 ; J12.4 97.62,76.5 ; J12.4 96.64,77.48 ; J36.4 117.4,21.84 ; J36.4 115.95,21.84 ; J36.4 116.67,22.57 ; J36.4 116.67,21.12 ; 125.69,63.61 J25.2 ; J25.2 126.39,64.32 ; J25.2 127.09,63.61 ; J17.26 21.88,16.08 ; J17.26 21,15.2 ; J17.26 22.75,15.2 ; J17.26 21.88,14.32
  ART03 w0.508: 122.26,63.49 J23.2 ; J23.2 123.52,63.49 ; J23.2 122.89,64.12 ; 106.17,21.12 J35.4 ; J35.4 105.44,21.84 ; J35.4 106.89,21.84 ; J35.4 106.17,22.57 ; J11.2 86.87,85.7 ; J11.2 86.87,83.74 ; J11.2 87.85,84.72 ; J11.2 85.89,84.72 ; 115.95,21.84 J36.4 ; J36.4 117.4,21.84 ; J36.4 116.67,22.57 ; J36.4 116.67,21.12 ; 123.5,65.72 SS3.1 ; SS3.1 123.5,72.28 ; SS3.1 126.78,69 ; SS3.1 120.22,69 ; 14,76.2 J1.2 ; J1.2 13.27,77.67 ; J1.2 14.73,77.67 ; J16.4 96.39,28.57 ; J16.4 95.66,29.3 ; J16.4 94.93,28.57 ; J16.4 95.66,27.85 ; SS2.1 123.5,14.28 ; SS2.1 126.78,11 ; SS2.1 120.22,11 ; J13.4 113.6,77.48 ; J13.4 113.6,75.52 ; J13.4 112.62,76.5 ; J13.4 114.58,76.5 ; 42.02,82.5 J5.2 ; J5.2 42.8,83.68 ; J5.2 43.57,82.5 ; J5.2 42.8,81.32 ; 10.22,11 SS1.1 16.78,11 ; 116.67,27.85 J27.8 ; J27.8 116.67,29.3 ; J27.8 115.95,28.57 ; J27.8 117.4,28.57 ; 113.95,28.57 J27.7 ; J27.7 114.67,27.85 ; J27.7 114.67,29.3 ; J27.7 115.4,28.57 ; J25.2 127.09,63.61 ; J25.2 125.69,63.61 ; J25.2 126.39,64.32 ; J1.3 19.3,79.15 ; J1.3 19.3,76.2 ; J1.3 20.03,77.67 ; J32.4 96.39,21.84 ; J32.4 95.66,21.12 ; J32.4 95.66,22.57 ; J32.4 94.93,21.84 ; J15.3 3.25,83.29 ; J15.3 2.28,84.26 ; J15.3 2.28,82.31 ; J15.3 1.3,83.29
  ART04 w0.152: 12.4,40.79 12.43,40.82 13.96,40.82 ; 9.96,31.06 10.87,31.06
  ART04 w0.254: 11.23,39.24 10.89,38.9 10.89,36.26 11.51,35.64 11.51,33.36 v1(12.21,32.65) ; 11.23,39.24 10.89,39.58 10.89,40.26 v1(10.36,40.79) 12.4,40.79 ; 11.23,39.24 15.09,39.24 15.88,40.03 15.88,44.5 14.57,45.81 7.92,45.81 7.25,45.14 7.25,28.43 7.72,27.96 10.64,27.96 11.81,29.13 11.81,30.83 11.58,31.06 10.87,31.06 ; 13.96,40.82 14.3,41.16 14.3,43.74 v1(13.84,44.19) 13.31,43.66 9.04,43.66 8.72,43.34 8.72,31.51 9.17,31.06 9.96,31.06
  ART04 w0.508: J35.4 106.89,21.84 ; J35.4 106.17,22.57 ; J35.4 105.44,21.84 ; J35.4 106.17,21.12 ; 42.02,82.5 J5.2 ; J5.2 42.8,81.32 ; J5.2 42.8,83.68 ; J5.2 43.57,82.5 ; J25.2 126.39,64.32 ; J25.2 125.69,63.61 ; J25.2 127.09,63.61 ; J1.3 20.03,77.67 ; J1.3 19.3,76.2 ; J1.3 19.3,79.15 ; J1.3 18.57,77.67 ; J27.7 114.67,29.3 ; J27.7 115.4,28.57 ; J27.7 113.95,28.57 ; J27.7 114.67,27.85 ; 2.28,82.31 J15.3 ; J15.3 2.28,84.26 ; J15.3 3.25,83.29 ; J15.3 1.3,83.29 ; SS4.1 13.5,72.28 ; SS4.1 16.78,69 ; SS4.1 10.22,69 ; SS2.1 123.5,14.28 ; SS2.1 126.78,11 ; SS2.1 120.22,11 ; J1.2 14.73,77.67 ; J1.2 14,79.15 ; J1.2 13.27,77.67 ; J1.2 14,76.2 ; 16.78,11 SS1.1 10.22,11 ; 123.5,65.72 SS3.1 ; SS3.1 126.78,69 ; SS3.1 123.5,72.28
  BOTTOM w0.254: C66.2 v1(77.85,83.63) ; C161.2 119.76,41.53 119.25,42.04 v1(118.97,42.04) ; v1(97.1,13.76) 97.18,13.84 R111.2 ; v1(115.87,59.71) 115.65,59.93 C117.2 ; D48.2 D49.2 D50.2 D51.2 D52.2 D53.2 ; R38.1 v1(45.21,74.81) ; L2.2 v1(17.18,81.6) ; L10.1 v1(69.6,84.26) ; U15.4 v1(108.45,63.06) 107.62,63.06 C119.2 107.06,63.43 105.03,63.43 104.86,63.27 104.86,59.63 105.03,59.47 ; v1(61.67,75.9) 61.66,75.89 D4.2 ; C52.2 v1(60.26,78.55) ; J18.8 v1(62.68,13.36) ; D12.1 v1(34.04,66.57) ; C89.2 v1(32.89,28.07) ; v1(97.1,15.76) 97.5,15.37 D61.2 ; v1(15.11,53.74) 15.01,53.84 C51.2 ; J18.6 v1(63.68,13.36) ; C157.2 v1(125.73,30.35) ; D3.2 62.8,75.89 v1(62.82,75.9) ; D58.2 v1(105.87,33.6) ; 0.78,62.78 0.78,61.78 v1(1.78,61.78) 1.81,61.81 J30.25 ; D26.2 v1(117.81,82) ; R112.2 v1(110.43,10.55) ; v1(86.59,53.72) 86.59,54.23 86.33,54.48 84.96,54.48 84.7,54.22 R173.2 ; D1.2 65.09,75.89 v1(65.1,75.9) ; R121.2 v1(82.96,13.84) ; D41.2 v1(72.39,10.95) ; C40.2 v1(54.43,79.36) ; R27.1 v1(49.91,76.31) ; R29.2 v1(54.43,80.37) ; R50.2 39.23,71.13 ; L12.1 v1(112.18,82.95) ; D42.2 v1(74.42,10.95) ; C75.2 v1(119.25,82) ; U7.2 v1(75.56,82.45) ; J28.4 5.38,38.75 ; C36.2 v1(54.86,78.34) ; C50.2 v1(52.45,84.44) ; v1(63.96,75.9) 63.95,75.89 D2.2 ; C33.2 v1(49.96,81.39) ; J24.4 3.89,21.36 v1(2.89,22.36) ; C53.2 60.26,75.89 v1(60.28,75.9) ; D27.2 v1(116.41,82) ; D8.2 59.25,75.87 v1(59.28,75.9) ; Q2.2 v1(124.28,51.84) ; v1(55.98,75.9) 55.95,75.87 D7.2 ; U26.5 v1(94.23,14.98) ; D39.2 v1(80.39,10.95) ; D56.2 v1(110.44,33.6) ; C67.2 v1(78.87,83.63) ; D57.2 v1(108.16,33.6) ; v1(9.18,56.81) 9.26,56.9 C135.2 C134.2 ; C131.2 C133.2 ; C158.2 v1(121.55,31.01) ; v1(58.18,75.9) 58.23,75.84 D5.2 ; D59.2 v1(103.58,33.6) ; C98.2 29.45,22.6 C99.2 ; D68.2 v1(84.7,15.37) ; R59.2 v1(80.9,81.19) ; C90.2 v1(32.89,29.08) ; D40.2 v1(76.45,10.95) ; v1(32.51,66.57) D11.1 ; R57.2 v1(70.99,83.75) ; D6.2 57.09,75.89 v1(57.08,75.9) ; J30.4 5.43,73.51 ; C159.2 v1(125.48,41.53) ; C65.2 v1(73.28,81.29) ; R138.2 v1(124.97,50.54) ; C93.2 v1(32.89,27.05)
  BOTTOM w0.508: 10.22,11 SS1.1 16.78,11 ; 95.66,27.85 J16.4 ; J16.4 95.66,29.3 ; J16.4 94.93,28.57 ; J16.4 96.39,28.57 ; J35.4 106.17,22.57 ; J35.4 105.44,21.84 ; J35.4 106.17,21.12 ; J35.4 106.89,21.84 ; 114.67,27.85 J27.7 ; J27.7 113.95,28.57 ; J27.7 114.67,29.3 ; J27.7 115.4,28.57 ; 2.28,82.31 J15.3 ; J15.3 1.3,83.29 ; J15.3 2.28,84.26 ; J11.2 86.87,85.7 ; J11.2 86.87,83.74 ; J11.2 87.85,84.72 ; J11.2 85.89,84.72 ; J18.32 69.31,11.8 ; J18.32 68.33,12.98 ; J18.32 68.33,10.62 ; J18.32 67.35,11.8 ; 94.93,21.84 J32.4 ; J32.4 95.66,21.12 ; J32.4 95.66,22.57 ; J32.4 96.39,21.84 ; 116.67,27.85 J27.8 ; J27.8 116.67,29.3 ; J27.8 115.95,28.57 ; J27.8 117.4,28.57 ; J29.25 5.03,44.45 ; J29.25 2.67,44.45 ; J29.25 3.85,43.47 ; J29.25 3.85,45.42 ; 113.6,75.52 J13.4 114.58,76.5 ; 76.17,72.94 J9.7 ; J9.7 76.17,74.4 ; J9.7 76.9,73.67 ; J9.7 75.44,73.67 ; J1.2 14.73,77.67 ; J1.2 13.27,77.67 ; J1.2 14,76.2 ; J5.2 43.57,82.5 ; J5.2 42.02,82.5 ; J5.2 42.8,81.32 ; J18.31 49.53,12.98 ; J18.31 49.53,10.62 ; J18.31 48.55,11.8 ; J17.5 42.75,17.2 ; J17.5 41.88,18.08 ; J17.5 41.88,16.32 ; J17.5 41,17.2 ; 95.66,76.5 J12.4 ; J12.4 96.64,77.48 ; J12.4 97.62,76.5 ; J12.4 96.64,75.52 ; 73.4,75.17 J9.4 71.94,75.17 ; J17.26 21.88,16.08 ; J17.26 22.75,15.2 ; J17.26 21,15.2 ; J28.26 3.85,42.93 ; J28.26 3.85,40.97 ; J28.26 2.67,41.95 ; J30.25 5.03,61.81 ; J30.25 3.85,60.84 ; J30.25 3.85,62.79 ; J17.4 43.88,16.08 ; J17.4 43,15.2 ; J17.4 44.75,15.2 ; 3.85,75.74 J30.26 ; J30.26 5.03,76.71 ; J30.26 2.67,76.71 ; J30.26 3.85,77.69 ; 33,15.2 J17.14 ; J17.14 34.75,15.2 ; J17.14 33.88,16.08 ; J23.2 122.89,64.12 ; J23.2 123.52,63.49 ; J23.2 122.26,63.49 ; J28.25 3.85,28.03 ; J28.25 2.67,27.05 ; J28.25 5.03,27.05 ; J1.3 20.03,77.67 ; J1.3 18.57,77.67 ; J1.3 19.3,79.15 ; J1.3 19.3,76.2 ; J25.2 127.09,63.61 ; J25.2 126.39,64.32 ; J25.2 125.69,63.61 ; J29.26 3.85,60.32 ; J29.26 3.85,58.37 ; J29.26 5.03,59.35 ; J29.26 2.67,59.35 ; J17.6 41.88,16.08 ; J17.6 42.75,15.2 ; J17.6 41,15.2 ; 21.88,16.32 J17.25 ; J17.25 22.75,17.2 ; J17.25 21,17.2 ; SS2.1 126.78,11 ; SS2.1 120.22,11 ; SS2.1 123.5,14.28 ; J17.13 34.75,17.2 ; J17.13 33,17.2 ; J17.13 33.88,18.08 ; J17.13 33.88,16.32 ; SS3.1 126.78,69 ; SS3.1 123.5,72.28 ; SS3.1 123.5,65.72 ; SS3.1 120.22,69 ; 2.67,9.66 J24.25 ; J24.25 5.03,9.66 ; J24.25 3.85,10.64 ; J36.4 116.67,22.57 ; J36.4 116.67,21.12 ; J36.4 115.95,21.84 ; SS4.1 16.78,69 ; SS4.1 13.5,72.28 ; SS4.1 10.22,69 ; SS4.1 13.5,65.72 ; 2.67,24.56 J24.26 3.85,23.58
  vias: v1(0.79,81.81) v1(0.79,78) v1(0.79,74.19) v1(0.78,72.27) v1(0.79,66.57) v1(0.79,62.76) v1(0.79,58.95) v1(0.79,51.33) v1(0.79,47.52) v1(0.79,43.71) v1(0.79,39.9) v1(0.79,32.28) v1(0.79,20.85) v1(0.79,17.04) v1(1.37,31.14) v1(1.38,28.75) v1(1.36,13.36) v1(1.36,12.36) v1(1.36,11.36) v1(1.5,19.68) v1(1.5,15.8) v1(1.57,84.62) v1(1.78,59.97) v1(2.36,51.65) v1(2.36,50.65) v1(2.36,49.15) v1(2.36,48.15) v1(2.36,47.15) v1(2.36,46.15) v1(2.38,28.75) v1(2.36,13.36) v1(2.36,12.36) v1(2.36,11.36) v1(2.46,23.32) v1(2.84,33.81) v1(3.12,54.3) v1(3.3,32.13) v1(3.36,57.65) v1(3.36,56.65) v1(3.36,49.15) v1(3.36,48.15) v1(3.36,47.15) v1(3.36,46.15) v1(3.38,28.75) v1(3.38,18.95) v1(3.36,13.36) v1(3.36,12.36) v1(3.36,11.36) v1(3.66,16.89) v1(4.43,75.51) v1(4.36,57.65) v1(4.36,56.65) v1(4.36,49.15) v1(4.36,48.15) v1(4.72,86.21) v1(5.11,68.73) v1(5.38,34.25) v1(5.38,31.98) v1(5.38,28.75) v1(5.44,16.84) v1(8.18,53.81) v1(8.18,52.81) v1(8.18,51.81) v1(8.53,86.21) v1(8.5,8.79) v1(9.62,10.78) v1(9.62,9.78) v1(10.36,39.79) v1(10.36,24.29) v1(10.36,23.29) v1(10.51,62.83) v1(10.64,18.69) v1(12.21,34.65) v1(12.21,33.65) v1(12.34,86.21) v1(13.11,55.74) v1(13.08,23) v1(13.21,34.65) v1(13.59,49) v1(13.59,48) v1(14.15,61.83) v1(14.11,55.74) v1(14.21,34.65) v1(14.21,33.65) v1(14.21,32.65) v1(14.59,49) v1(14.59,48) v1(15.15,62.83) v1(15.15,61.83) v1(15.11,55.74) v1(15.11,54.74) v1(15.11,52.74) v1(15.7,20.55) v1(16.15,61.83) v1(16.15,60.83) v1(16.15,86.21) v1(16.54,30.78) v1(16.65,66.83) v1(17.15,65.83) v1(17.18,82.6) v1(17.42,27.02) v1(17.45,25.65) v1(17.47,23.83) v1(17.65,66.83) v1(18.18,82.6) v1(18.18,81.6) v1(19.46,22.68) v1(19.65,61.83) v1(19.93,8.79) v1(20.32,20.55) v1(20.4,75.28) v1(20.37,27.05) v1(20.46,22.68) v1(20.57,80.12) v1(20.57,79.12) v1(20.65,63.83) v1(20.65,62.83) v1(20.65,61.83) v1(20.68,55.69) v1(20.68,54.69) v1(20.68,53.69) v1(20.68,52.69) v1(21.4,77.28) v1(21.4,76.28) v1(21.4,75.28) v1(21.54,12.27) v1(21.57,83.12) v1(21.57,82.12) v1(21.57,81.12) v1(21.57,80.12) v1(21.65,66.83) v1(21.65,65.83) v1(21.65,64.83) v1(21.65,62.83) v1(21.65,61.83) v1(21.65,60.83) v1(21.72,29.87) v1(22.54,12.27) v1(22.63,20.55) v1(23.14,28.03) v1(23.14,27.03) v1(23.14,26.03) v1(23.4,74.28) v1(23.54,12.27) v1(23.57,84.99) v1(23.74,8.79) v1(24.14,28.03) v1(24.14,27.03) v1(24.14,26.03) v1(24.14,25.03) v1(24.4,74.28) v1(24.4,73.28) v1(24.4,72.28) v1(24.54,12.27) v1(24.68,55.69) v1(24.87,46.1) v1(25.14,28.03) v1(25.14,27.03) v1(25.14,26.03) v1(25.14,25.03) v1(25.2,61.7) v1(25.4,74.28) v1(25.4,73.28) v1(25.4,72.28) v1(25.54,12.27) v1(25.68,55.69) v1(25.68,52.69) v1(25.68,51.69) v1(26.14,28.03) v1(26.14,26.03) v1(26.14,25.03) v1(26.33,65.7) v1(26.33,64.7) v1(26.33,62.7) v1(26.54,12.27) v1(26.68,55.69) v1(26.68,54.69) v1(26.68,53.69) v1(26.68,52.69) v1(26.68,51.69) v1(26.94,66.6) v1(27.33,61.7) v1(27.54,12.27) v1(27.55,8.79) v1(27.74,46.1) v1(27.94,66.6) v1(28.54,12.27) v1(28.89,72.77) v1(29.46,66.6) v1(29.51,38.18) v1(29.54,12.27) v1(30.51,41.71) v1(30.51,38.18) v1(31.36,8.79) v1(31.51,38.18) v1(31.52,20.17) v1(31.68,52.69) v1(31.68,51.69) v1(31.88,62.1) v1(31.88,61.1) v1(32.51,36.91) v1(32.59,64.72) v1(32.68,55.69) v1(32.68,54.69) v1(32.68,53.69) v1(32.68,52.69) v1(32.68,51.69) v1(32.68,50.69) v1(33.53,40.99) v1(33.53,38.99) v1(33.68,50.69) v1(33.91,65.81) v1(33.89,21.99) v1(33.89,20.99) v1(34.16,24) v1(34.65,60.96) v1(34.57,53.08) v1(34.57,28.04) v1(34.57,26.03) v1(34.67,63.97) v1(34.67,62.97) v1(34.67,58.42) v1(34.68,50.69) v1(34.8,73) v1(34.9,68.3) v1(34.89,21.99) v1(34.89,20.99) v1(35.17,8.79) v1(35.9,68.3) v1(35.89,21.99) v1(35.89,20.99) v1(36.89,21.99) v1(36.89,20.99) v1(37.31,55.78) v1(37.31,52.68) v1(37.36,73.68) v1(37.44,30.33) v1(37.47,31.75) v1(38.16,27.8) v1(38.29,26.2) v1(38.29,25.2) v1(38.29,24.2) v1(38.35,65.4) v1(38.98,8.79) v1(39.16,54.89) v1(39.16,42.3) v1(39.34,66.95) v1(39.5,32.93) v1(39.5,29.33) v1(39.6,19.94) v1(39.66,53.47) v1(39.68,37.92) v1(39.8,56.7) v1(39.94,27.8) v1(40.23,72.13) v1(40.23,71.13) v1(40.16,42.3) v1(40.21,24.18) v1(40.33,86.21) v1(40.34,66.95) v1(40.34,57.73) v1(40.5,59.39) v1(40.5,52.19) v1(40.5,50.3) v1(40.51,47.8) v1(40.5,44.99) v1(40.64,55.07) v1(40.66,53.47) v1(40.67,40.77) v1(40.8,56.7) v1(41.02,77.95) v1(41.02,76.95) v1(41.02,75.95) v1(41.02,74.95) v1(41.23,72.13) v1(41.23,71.13) v1(41.16,42.3) v1(41.5,64.72) v1(41.5,44.99) v1(41.64,55.07) v1(41.63,25.2) v1(41.66,53.47) v1(41.73,28.8) v1(41.78,33.43) v1(41.78,32.28) v1(41.78,31.28) v1(41.78,30.28) v1(42.23,72.13) v1(42.23,71.13) v1(42.64,55.07) v1(42.8,65.78) v1(42.82,52.98) v1(42.79,8.79) v1(42.95,24) v1(43.21,74.81) v1(43.36,36.32) v1(43.36,35.32) v1(43.36,33.43) v1(43.36,32.43) v1(43.36,31.43) v1(43.36,30.43) v1(43.36,29.43) v1(43.36,28.43) v1(43.38,19.96) v1(43.61,63.48) v1(43.61,62.48) v1(43.61,61.48) v1(43.61,60.48) v1(43.61,59.48) v1(43.61,58.48) v1(43.61,57.48) v1(43.64,55.07) v1(43.61,50.32) v1(43.59,44.96) v1(43.59,43.96) v1(43.61,42.32) v1(43.64,40.77) v1(44.86,31.86) v1(44.86,30.86) v1(44.86,29.86) v1(44.86,28.86) v1(44.86,27.86) v1(45.11,26.14) v1(45.11,24.94) v1(45.21,76.81) v1(45.21,75.81) v1(45.67,67.51) v1(45.85,65.81) v1(45.85,64.81) v1(45.85,63.81) v1(45.85,62.81) v1(45.85,61.81) v1(45.82,59.49) v1(45.82,58.49) v1(45.82,57.49) v1(46.1,19.96) v1(46.6,8.79) v1(46.69,31.85) v1(46.69,30.85) v1(46.69,29.85) v1(46.69,28.85) v1(46.69,27.85) v1(46.66,23.9) v1(46.79,52.98) v1(46.79,51.98) v1(46.79,50.98) v1(46.79,49.98) v1(46.84,44.98) v1(46.84,43.98) v1(46.84,42.26) v1(46.84,40.74) v1(47.45,17.93) v1(47.45,16.93) v1(47.45,15.93) v1(47.45,14.93) v1(47.45,13.93) v1(47.95,86.21) v1(48.06,44.98) v1(48.06,43.98) v1(48.08,42.26) v1(48.08,40.74) v1(48.08,39.74) v1(48.08,38.74) v1(48.08,37.74) v1(48.08,36.74) v1(48.08,35.74) v1(48.08,34.74) v1(48.08,31.83) v1(48.08,30.83) v1(48.08,29.83) v1(48.08,28.83) v1(48.08,27.83) v1(49,25.96) v1(49,24.94) v1(49,23.77) v1(49.83,79.71) v1(49.83,78.71) v1(49.96,82.39) v1(50.41,8.79) v1(50.85,67.82) v1(50.85,66.82) v1(50.85,65.82) v1(50.9,62.53) v1(51.08,10.32) v1(51.41,54.02) v1(51.41,52.75) v1(51.41,51.48) v1(51.41,50.21) v1(51.41,48.94) v1(51.41,47.67) v1(51.41,46.4) v1(51.41,45.13) v1(51.9,62.53) v1(52.12,39.4) v1(52.68,13.36) v1(52.9,62.53) v1(52.93,59.49) v1(53.39,39.4) v1(53.45,83.42) v1(53.52,54) v1(53.52,52.73) v1(53.52,51.46) v1(53.52,50.19) v1(53.52,48.92) v1(53.52,47.65) v1(53.52,46.38) v1(54.18,13.36) v1(54.22,8.79) v1(55.43,80.39) v1(55.57,86.21) v1(55.68,13.36) v1(55.94,66.27) v1(56.49,11.55) v1(57.18,13.36) v1(58.03,8.79) v1(58.72,13.36) v1(59.38,86.21) v1(60.12,13.36) v1(61.84,8.79) v1(62.48,10.47) v1(63.13,28.76) v1(63.13,27.76) v1(63.19,86.21) v1(63.48,10.47) v1(64.13,28.76) v1(64.13,27.76) v1(64.48,10.47) v1(64.68,13.36) v1(65.13,28.76) v1(65.13,27.76) v1(65.48,44.27) v1(65.48,41.15) v1(65.51,39.22) v1(66.04,13.33) v1(66.55,59.59) v1(66.75,44.27) v1(66.75,41.15) v1(66.78,39.22) v1(67.31,53.44) v1(67.31,52.17) v1(67.6,84.26) v1(67.6,83.26) v1(68.6,84.26) v1(68.6,83.26) v1(69.03,13.48) v1(69.11,70.76) v1(69.46,8.79) v1(70.03,11.48) v1(70.11,70.76) v1(70.81,86.21) v1(71.03,11.48) v1(71.11,70.76) v1(71.4,13.5) v1(72.4,13.5) v1(72.57,78.04) v1(73.3,18.19) v1(73.27,8.79) v1(73.4,13.5) v1(73.57,78.04) v1(73.66,59.03) v1(74.62,86.21) v1(74.57,82.45) v1(74.57,78.04) v1(74.9,24.7) v1(74.9,23.7) v1(75.4,13.5) v1(75.56,78.04) v1(76.56,78.04) v1(76.83,58.6) v1(77.08,8.79) v1(77.49,23.71) v1(77.56,78.04) v1(78.43,86.21) v1(78.42,61.65) v1(78.4,13.5) v1(78.4,12.5) v1(78.49,23.71) v1(78.56,78.04) v1(79.88,84.63) v1(80.74,68.25) v1(80.89,8.79) v1(82.24,86.21) v1(82.3,84.49) v1(82.68,49.88) v1(82.86,32.3) v1(82.86,26.3) v1(82.86,25.3) v1(83.74,68.25) v1(84.74,68.25) v1(84.82,19.42) v1(85.42,29.3) v1(85.42,28.3) v1(85.42,27.3) v1(85.42,26.3) v1(85.42,25.3) v1(85.63,77.76) v1(86.05,86.21) v1(86.63,77.76) v1(86.84,63.9) v1(87.84,42.71) v1(88.51,8.79) v1(88.75,69.59) v1(88.83,55.71) v1(88.84,42.71) v1(89.06,40.66) v1(89.51,76.52) v1(89.51,75.52) v1(89.84,63.9) v1(89.86,86.21) v1(89.87,68.9) v1(90.87,68.9) v1(91.41,61.95) v1(91.41,60.95) v1(92.23,26.75) v1(92.32,8.79) v1(92.41,61.95) v1(92.41,60.95) v1(93.23,26.75) v1(93.44,9.78) v1(93.67,86.21) v1(94.23,26.75) v1(94.23,15.98) v1(94.29,63.42) v1(94.4,56.4) v1(94.47,64.77) v1(94.6,70.62) v1(94.6,69.62) v1(94.64,58.7) v1(95.2,39.67) v1(95.2,38.67) v1(95.23,26.75) v1(95.33,64.77) v1(95.35,55.83) v1(95.35,54.83) v1(96.77,62.15) v1(97.2,39.67) v1(97.48,86.21) v1(97.83,9.65) v1(98.2,39.67) v1(98.2,38.67) v1(98.43,62.08) v1(98.83,9.65) v1(98.88,51.88) v1(98.88,18.39) v1(99.83,9.65) v1(99.88,18.39) v1(99.94,8.79) v1(100.24,46.68) v1(100.83,9.65) v1(101.15,64.13) v1(101.29,86.21) v1(101.91,18.39) v1(103.75,8.79) v1(103.91,18.39) v1(104.99,13.71) v1(105.1,86.21) v1(105.21,58.86) v1(106.21,58.86) v1(106.4,18.39) v1(106.45,16.03) v1(107.21,58.86) v1(107.4,18.39) v1(107.45,16.03) v1(108.21,59.86) v1(108.21,58.86) v1(108.4,18.39) v1(108.45,16.03) v1(108.91,86.21) v1(109.21,59.86) v1(109.4,18.39) v1(109.5,68.73) v1(110.21,59.86) v1(110.31,54.2) v1(110.4,18.39) v1(110.63,14.22) v1(111.21,59.86) v1(111.17,12.22) v1(111.36,71.87) v1(111.36,70.87) v1(111.36,69.87) v1(111.4,18.39) v1(111.43,10.55) v1(111.37,8.79) v1(111.9,14.22) v1(112.02,40.26) v1(112.17,12.22) v1(112.4,18.39) v1(112.43,10.55) v1(112.72,86.21) v1(113.18,82.95) v1(113.16,71.88) v1(113.17,12.22) v1(113.43,10.55) v1(113.7,32.7) v1(113.7,31.7) v1(113.7,30.7) v1(113.97,50.89) v1(113.97,49.89) v1(114.18,82.95) v1(114.16,71.88) v1(114.17,12.22) v1(114.27,69.37) v1(114.3,68.12) v1(114.43,10.55) v1(114.97,50.89) v1(115.21,38.3) v1(115.17,12.22) v1(115.18,8.79) v1(115.27,69.37) v1(115.43,10.55) v1(116.03,66.52) v1(116.2,40.3) v1(116.17,12.22) v1(116.27,69.37) v1(116.53,86.21) v1(116.97,50.89) v1(117.17,13.22) v1(117.17,12.22) v1(117.91,45.3) v1(117.91,44.3) v1(117.91,32.05) v1(118.17,14.22) v1(118.9,54.43) v1(118.9,52.5) v1(118.9,51.5) v1(118.9,50.5) v1(118.91,45.3) v1(118.91,33.05) v1(118.97,43.04) v1(119.28,27.05) v1(119.7,59.31) v1(120.34,86.21) v1(120.7,59.31) v1(120.91,33.05) v1(121.06,16.52) v1(121.06,15.52) v1(121.7,59.31) v1(121.91,33.05) v1(122.7,59.31) v1(123.7,59.31) v1(123.83,39.11) v1(123.83,38.11) v1(124.15,86.21) v1(124.7,59.31) v1(125.01,23.65) v1(125.72,65.48) v1(126.01,23.65) v1(127.01,42.54) v1(127.01,23.65) v1(127.96,86.12) v1(128.71,82.39) v1(128.71,78.58) v1(128.71,74.77) v1(128.71,70.96) v1(128.71,67.15) v1(128.71,63.34) v1(128.71,55.72) v1(128.71,51.91) v1(128.71,44.29) v1(128.71,40.48) v1(128.71,32.86) v1(128.71,29.05) v1(128.71,25.24) v1(128.71,21.43) v1(128.71,17.62) v1(128.71,13.81) v1(128.71,10)
VCC3V3_SD: length 27.2
  TOP w0.381: v1(59.59,73.1) J7.4 ; v1(82.86,29.8) 82.96,29.7 J3.8
  BOTTOM w0.381: v1(68.09,72.28) 68.08,72.27 66.65,72.27 66.34,72.58 66.34,79 65.62,79.73 59.88,79.73 59.26,79.11 59.26,77.21 59.65,76.83 C52.1 60.92,76.17 60.92,74.6 60.36,74.03 C53.1 D8.1 59.25,73.44 v1(59.59,73.1)
VCC3V3_WIFI: length 15.8
  TOP w0.254: R164.1 v1(98.3,65.91) ; v1(103.63,53.95) 104.22,53.37 104.22,51.82 C123.1 103.58,49.78 Y4.4 ; R151.1 v1(118.7,56.89)
  TOP w0.508: v1(101.51,69.1) v1(102.51,69.1) 104.54,69.1 104.95,69.51 C121.1 C122.1 U16.9
  vias: v1(100.86,58.71) v1(100.86,57.71)
VCC5V0_SYS: length 86.4
  TOP w0.254: v1(82.86,24.3) J3.2 v1(85.42,24.3)
  ART04 w0.254: v1(2.52,80.86) 2.55,80.86 3.25,80.16 3.25,77.14 3.89,76.5 7.42,76.5 8.53,75.39 19.15,75.39 19.66,74.88 19.66,71.17 20.24,70.59 46.61,70.59 47.19,71.17 v1(47.19,74.83)
  BOTTOM w0.254: v1(47.19,74.83) 52.7,74.83 53.21,74.32 53.21,72.13 53.7,71.65 64.69,71.65 65.09,72.05 v1(65.09,72.1) ; v1(27.68,54.69) 27.68,56.26 26.92,57.02 C12.2 R5.2 ; R12.1 v1(2.52,80.86)
  vias: v1(27.68,53.69) v1(27.68,52.69) v1(27.68,51.69) v1(28.68,52.69) v1(28.68,51.69) v1(82.86,23.3) v1(84.05,22.3) v1(85.42,23.3) v1(85.42,22.3)
VCC5V0_USB: length 9
  BOTTOM w0.254: R6.2 C15.2 24.71,61.23 24.71,56.51 24.46,56.26 23.26,56.26 v1(22.68,55.69)
  vias: v1(21.68,55.69) v1(21.68,54.69) v1(21.68,53.69) v1(21.68,52.69) v1(22.68,52.69) v1(75.72,84.75) v1(75.72,83.63) v1(76.85,84.75) v1(77.85,84.75) v1(109.54,48.75) v1(110.54,48.75) v1(111.54,48.75) v1(111.54,47.75)
VCC5V0_USB20_HUB: length 13.3
  TOP w0.254: C137.1 J38.4
  TOP w0.508: C80.1 102.49,75.35 J12.1
  BOTTOM w0.254: C75.1 v1(120,80.26)
  BOTTOM w0.508: J13.1 119.25,77.85 C75.1
  vias: v1(103.5,72.87) v1(103.5,71.87) v1(115.21,39.3) v1(116.2,39.3) v1(117.91,48.3) v1(118.91,48.3) v1(119.91,49.3) v1(119.91,48.3) v1(121,80.26)
VCC_LVDS: length 39.5
  TOP w0.508: J20.2 J20.4 J20.6 ; J17.3 J17.1
  BOTTOM w0.381: J20.2 15.5,15.16 16.76,13.89 44.57,13.89 J17.2 J17.1
VCC_RTC: length 20.5
  TOP w0.254: v1(119.7,64.13) 119.7,66.74 119.27,67.17 v1(118.7,67.17)
  BOTTOM w0.254: D43.3 118.94,63.38 v1(119.7,64.13) ; R130.1 R131.1 112.22,66.91 112.47,67.17 v1(118.7,67.17)
  BOTTOM w0.305: D43.3 116.32,63.38 C117.1 115.11,62.71 114.81,62.41 114.81,61.3 114.62,61.11 U15.8
VCCA_1V8: length 35.1
  TOP w0.254: v1(100.79,43.81) 100.79,48.89 100.05,49.63 95.38,49.63 94.95,50.06 v1(94.95,51.88)
  TOP w0.381: J3.7 v1(82.86,28.8)
  ART04 w0.508: 102.67,27.85 J27.1 ; J27.1 102.67,29.3 ; J27.1 101.95,28.57 ; J27.1 103.4,28.57
  BOTTOM w0.254: v1(94.95,51.88) 90.54,51.88 89.91,52.51 84.89,52.51 R171.1 ; 63.15,19.41 v1(63.15,19.41)
  BOTTOM w0.508: v1(65.12,25.1) 65.12,20.24 64.64,19.76 63.5,19.76 63.15,19.41
  vias: v1(63.15,18.41) v1(65.13,26.17) v1(82.86,27.8)
VCCIO_ACODEC: length 26.3
  TOP w0.381: J3.9 83.06,30.6 v1(82.86,30.8)
  BOTTOM w0.381: R18.2 54.63,82.3 66.45,82.3 67.16,81.59 67.16,73.49 67.44,73.21 68.73,73.21 69.09,72.85 v1(69.09,72.28)
VDD_3V3: length 103.2
  TOP w0.203: U22.1 C136.1 ; v1(18.44,50.88) 18.41,50.85 U22.5 ; v1(18.44,45.92) 18.41,45.9 U21.5 ; C128.1 U21.1
  TOP w0.254: U27.3 13.74,28.51 13.41,28.18 13.41,26.94 13.74,26.61 U27.1 ; U11.5 7.77,73.17 C85.1 7.03,72.43 4,72.43 C81.1 ; C81.1 3.58,73.17 U12.5 ; C81.1 3.42,72.99 2.7,72.27 v1(1.78,72.27) ; C136.1 17.92,48.25 18.83,47.34 v1(18.92,47.34) ; J21.4 v1(74.4,14.5)
  TOP w0.305: C107.1 19.19,37.83 U17.24
  TOP w0.381: v1(88.83,54.71) 88.82,54.73 C68.1 R60.1 ; L13.1 32.12,33.7 C111.1 v1(32.12,35.36) ; L14.2 v1(88.06,37.31) ; U27.1 15.49,26.61 v1(15.54,26.55) ; L16.2 100.77,38.67 v1(99.46,38.67) ; R260.1 v1(123.06,15.52)
  BOTTOM w0.254: R80.1 R82.1 9.26,22.04 9.52,22.29 v1(10.36,22.29) ; v1(16.11,54.74) 16.46,54.74 16.97,55.25 16.97,60.68 17.22,60.93 18.54,60.93 18.8,61.19 R14.2 C25.2 ; R31.2 v1(52.45,83.42) ; D42.1 74.42,13.48 v1(74.4,13.5) v1(74.4,14.5) ; R189.1 R175.1 R174.1 ; R189.1 v1(67.31,58.65) ; R189.1 R190.1 ; v1(16.11,55.74) 16.11,60.09 15.27,60.93 8.52,60.93 8.26,61.19 R15.2 ; v1(17.11,53.74) 17.7,54.33 17.7,59.84 18.08,60.22 23.49,60.22 R10.2 ; R13.1 v1(7.61,80.86) ; v1(34.16,25) 34.33,25.17 R191.1 R192.1
  BOTTOM w0.381: U18.5 123.98,29.08 123.71,29.35 C157.1 123.71,30.46 124.28,31.04 126.04,31.04 v1(126.73,30.35) ; v1(32.12,35.36) 32.05,35.43 C110.1 ; v1(117.35,60.37) 117.35,60.86 D43.2 ; v1(20.32,23.98) 21.34,22.96 R78.1 ; 15.54,26.54 v1(15.54,26.55) ; 125.69,39.88 123.96,39.88 123.71,40.13 C159.1 v1(123.71,42.3) ; L17.1 v1(87,9.65) ; L15.1 v1(101.83,9.65)
  vias: v1(6.35,24.7) v1(6.35,23.7) v1(7.35,24.7) v1(7.35,23.7) v1(16.11,53.74) v1(16.11,52.74) v1(17.11,52.74) v1(17.51,42.16) v1(18.51,42.16) v1(99.15,64.13) v1(100.15,64.13) v1(122.06,15.52)
